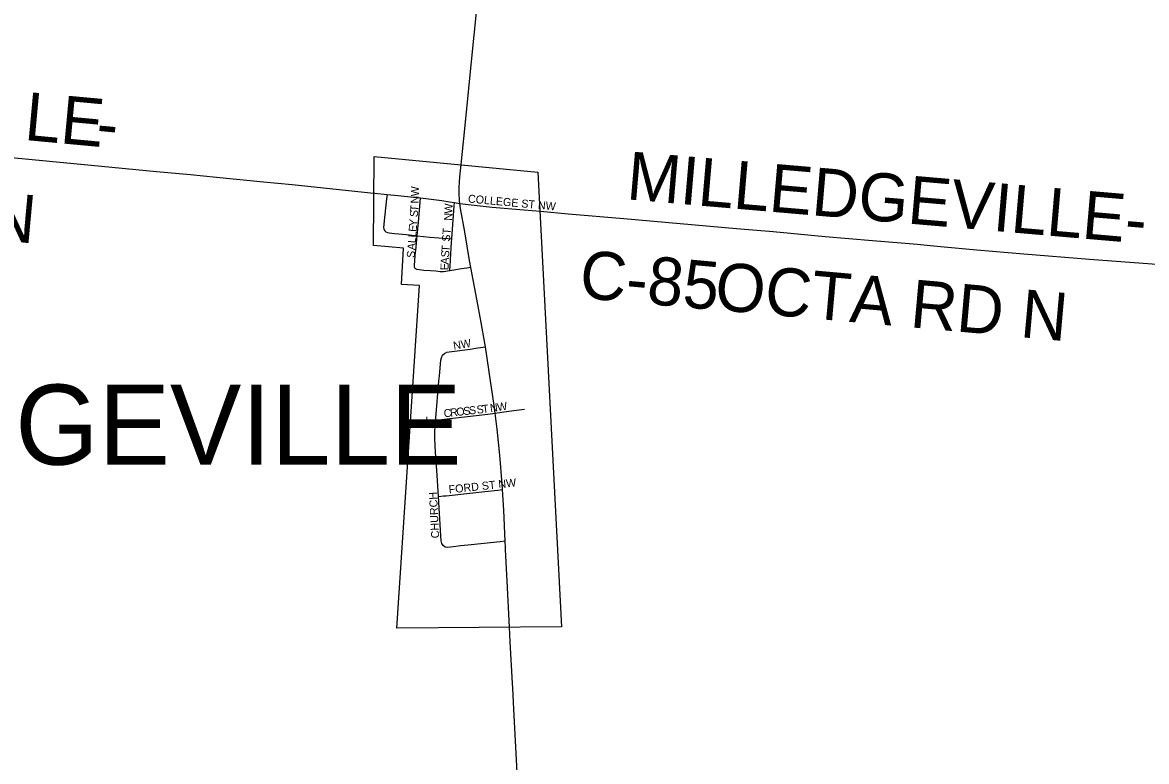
# Model space of a CAD drawing. Extents: x -49 to -8.2, y 9.4 to 23.5.
# Drawn here: x -40.683 to -40.018, y 16.323 to 16.76 of the extents above; entities that cross this region are included whole.
import ezdxf

# ---------------------------------------------------------------- set-up
doc = ezdxf.new("R2010")
doc.units = 0
for name, color, linetype in [('GM_X_City_Street', 7, 'Continuous'), ('GM_X_City_Street_Text', 7, 'Continuous'), ('GM_X_Corporation', 7, 'Continuous'), ('GM_X_Corporation_Text', 7, 'Continuous'), ('GM_X_County_Road', 7, 'Continuous'), ('GM_X_County_Road_Text', 7, 'Continuous'), ('GM_X_State_Route', 7, 'Continuous')]:
    doc.layers.add(name, color=color, linetype=linetype)

msp = doc.modelspace()

# ---------------------------------------------------------------- linework, layer by layer
at = {"layer": 'GM_X_City_Street'}
for points in [[(-40.47469, 16.65893), (-40.46752, 16.65819)], [(-40.46752, 16.65819), (-40.46779, 16.65552), (-40.46873, 16.64634), (-40.46958, 16.6387), (-40.46947, 16.63794), (-40.46922, 16.63723), (-40.46876, 16.63661), (-40.46815, 16.63617), (-40.46728, 16.6358), (-40.46623, 16.63551), (-40.46302, 16.63509), (-40.45607, 16.63447), (-40.44964, 16.6338)], [(-40.46752, 16.65819), (-40.461, 16.65752), (-40.45187, 16.65662), (-40.44779, 16.65613)], [(-40.44964, 16.6338), (-40.4487, 16.64402), (-40.44797, 16.65367), (-40.44779, 16.65613)], [(-40.44779, 16.65613), (-40.43516, 16.65461), (-40.43063, 16.65391), (-40.42764, 16.65339)], [(-40.42916, 16.63194), (-40.42778, 16.65143), (-40.42764, 16.65339)], [(-40.42764, 16.65339), (-40.42438, 16.65282)], [(-40.42438, 16.65282), (-40.41772, 16.65199), (-40.40529, 16.65072), (-40.38662, 16.64906), (-40.37681, 16.64827)], [(-40.43035, 16.613), (-40.43183, 16.61278), (-40.4328, 16.61263), (-40.43412, 16.61253), (-40.43603, 16.61252), (-40.43864, 16.61275), (-40.44186, 16.61304), (-40.44571, 16.61332), (-40.44987, 16.61379), (-40.45022, 16.61394), (-40.45048, 16.61415), (-40.45077, 16.61443), (-40.45101, 16.61475), (-40.45117, 16.61516), (-40.45124, 16.61549), (-40.4513, 16.61592), (-40.45133, 16.61624), (-40.45078, 16.62213), (-40.45032, 16.62702), (-40.44984, 16.63167), (-40.44964, 16.6338)], [(-40.44964, 16.6338), (-40.44224, 16.63304), (-40.43152, 16.63214), (-40.42916, 16.63194)], [(-40.43035, 16.613), (-40.43029, 16.61449), (-40.43024, 16.61545), (-40.42993, 16.61978), (-40.4293, 16.63001), (-40.42916, 16.63194)], [(-40.41786, 16.61498), (-40.42027, 16.61463), (-40.42337, 16.61419), (-40.42795, 16.61341), (-40.43035, 16.613)], [(-40.43865, 16.52482), (-40.43855, 16.52616), (-40.43678, 16.54782), (-40.43653, 16.5509), (-40.4356, 16.56017), (-40.43528, 16.56168), (-40.43465, 16.5631), (-40.43359, 16.56421), (-40.43219, 16.56486), (-40.43067, 16.56517), (-40.4276, 16.56561), (-40.41835, 16.56676), (-40.41374, 16.56743), (-40.40935, 16.56808)], [(-40.40358, 16.52887), (-40.3985, 16.52971), (-40.39083, 16.53068), (-40.38623, 16.53125)], [(-40.43696, 16.47966), (-40.43785, 16.49208), (-40.43878, 16.50602), (-40.43919, 16.51377), (-40.43915, 16.51843), (-40.43879, 16.52307), (-40.43865, 16.52482)], [(-40.43865, 16.52482), (-40.43377, 16.52534), (-40.41483, 16.52747), (-40.40794, 16.52827), (-40.40358, 16.52887)], [(-40.43696, 16.47966), (-40.43414, 16.47994), (-40.43261, 16.48009), (-40.42035, 16.48146), (-40.40963, 16.48257), (-40.40198, 16.4834), (-40.39917, 16.48371)], [(-40.39765, 16.45323), (-40.40067, 16.45289), (-40.41764, 16.45099), (-40.42381, 16.45036), (-40.42996, 16.4496), (-40.43152, 16.4495), (-40.43304, 16.44975), (-40.43435, 16.45055), (-40.43518, 16.45184), (-40.43553, 16.45335), (-40.43573, 16.45645), (-40.43696, 16.47966)]]:
    msp.add_lwpolyline(points, dxfattribs=at)
at = {"layer": 'GM_X_Corporation'}
msp.add_lwpolyline([(-40.47503, 16.68061), (-40.37833, 16.67144), (-40.36427, 16.4026), (-40.4618, 16.40178), (-40.4482, 16.60427), (-40.45886, 16.60498), (-40.45768, 16.62653), (-40.47546, 16.62795)], close=True, dxfattribs=at)
at = {"layer": 'GM_X_County_Road'}
for points in [[(-40.90135, 16.70783), (-40.89314, 16.70715), (-40.84518, 16.70339), (-40.81889, 16.70112), (-40.80964, 16.70005), (-40.80197, 16.69886), (-40.79285, 16.69703), (-40.7671, 16.69124), (-40.74738, 16.68698), (-40.73976, 16.68553), (-40.73209, 16.68433), (-40.72285, 16.68319), (-40.6425, 16.6756), (-40.60388, 16.67186), (-40.5838, 16.66994), (-40.56835, 16.66846), (-40.54056, 16.66566), (-40.52357, 16.66402), (-40.50505, 16.66203), (-40.47726, 16.65919), (-40.47469, 16.65893)], [(-40.37681, 16.64827), (-40.36037, 16.64683)], [(-40.36037, 16.64683), (-40.32733, 16.64395), (-40.26083, 16.63812), (-40.23917, 16.63624), (-40.20825, 16.63337), (-40.18042, 16.63097), (-40.1634, 16.62957), (-40.15393, 16.62872), (-40.14021, 16.62749), (-40.11857, 16.62553), (-40.09073, 16.62314), (-40.05205, 16.62001), (-39.99632, 16.61578), (-39.96691, 16.61352), (-39.94058, 16.61162), (-39.91949, 16.61001)]]:
    msp.add_lwpolyline(points, dxfattribs=at)
at = {"layer": 'GM_X_State_Route'}
for points in [[(-40.42367, 16.67584), (-40.42128, 16.69902), (-40.41705, 16.74076), (-40.41477, 16.76395), (-40.41235, 16.78713), (-40.4081, 16.82887), (-40.40739, 16.83604)], [(-40.39748, 16.44923), (-40.39765, 16.45323), (-40.39846, 16.47152), (-40.39917, 16.48371), (-40.39936, 16.48703), (-40.40085, 16.50406), (-40.40244, 16.51952), (-40.40358, 16.52887), (-40.40413, 16.5334), (-40.40707, 16.55338), (-40.40935, 16.56808), (-40.40969, 16.57028), (-40.41176, 16.58253), (-40.41434, 16.59628), (-40.41786, 16.61498), (-40.41865, 16.61921), (-40.42155, 16.63606), (-40.42401, 16.64985), (-40.42438, 16.65282), (-40.4246, 16.6545), (-40.42493, 16.65918), (-40.42493, 16.66232), (-40.42453, 16.66855), (-40.42367, 16.67584)], [(-40.39504, 16.40226), (-40.39647, 16.42959), (-40.39743, 16.44823), (-40.39748, 16.44923)], [(-40.39458, 16.39377), (-40.39504, 16.40226)], [(-40.39016, 16.30884), (-40.39248, 16.35382), (-40.3931, 16.36622), (-40.39326, 16.36932), (-40.39458, 16.39377)]]:
    msp.add_lwpolyline(points, dxfattribs=at)

# ---------------------------------------------------------------- texts
at = {"layer": 'GM_X_City_Street_Text'}
for s, height, rotation, p in [('W', 0.00473, 89.96073, (-40.44868, 16.6571)), ('N', 0.00473, 88.5966, (-40.44879, 16.65281)), ('COLLEGE ST NW', 0.0047348, 354.80647, (-40.41977, 16.65346)), ('T', 0.00473, 85.71008, (-40.44913, 16.64798)), ('W', 0.00473, 87.72157, (-40.4289, 16.64681)), ('Y', 0.00473, 85.73373, (-40.44978, 16.63925)), ('S', 0.00473, 85.72051, (-40.44938, 16.64466)), ('N', 0.00473, 87.33293, (-40.4291, 16.64261)), ('L', 0.00473, 85.7348, (-40.45028, 16.63261)), ('E', 0.00473, 85.7348, (-40.45003, 16.63593)), ('ST', 0.004735, 85.60322, (-40.43034, 16.63014)), ('A', 0.00473, 85.72478, (-40.45083, 16.62513)), ('L', 0.00473, 85.70607, (-40.45052, 16.62928)), ('S', 0.00473, 85.73332, (-40.45118, 16.62055)), ('S', 0.00473, 86.30949, (-40.43084, 16.62082)), ('T', 0.00473, 86.28223, (-40.43062, 16.62414)), ('E', 0.00473, 88.3876, (-40.43118, 16.61337)), ('A', 0.00473, 86.56679, (-40.43109, 16.61666)), ('NW', 0.004735, 9.46675, (-40.42794, 16.56637)), ('C', 0.00473, 6.35092, (-40.43372, 16.52637)), ('R', 0.00473, 6.35142, (-40.42999, 16.52679)), ('O', 0.00473, 6.35859, (-40.42627, 16.5272)), ('S', 0.00473, 6.35226, (-40.42212, 16.52767)), ('S', 0.00473, 6.34631, (-40.41881, 16.52804)), ('S', 0.00473, 6.34631, (-40.41426, 16.52854)), ('T', 0.00473, 6.34631, (-40.41094, 16.52891)), ('N', 0.00473, 7.56555, (-40.40628, 16.52943)), ('W', 0.00473, 9.38384, (-40.40199, 16.53)), ('S', 0.00473, 89.86338, (-40.43951, 16.51965)), ('T', 0.00473, 88.98915, (-40.43951, 16.52297)), ('FORD ST NW', 0.004735, 6.04412, (-40.43079, 16.48137)), ('CHURCH', 0.004735, 92.96295, (-40.4366, 16.45502))]:
    msp.add_text(s, height=height, rotation=rotation, dxfattribs=at).set_placement(p)
at = {"layer": 'GM_X_Corporation_Text'}
msp.add_text('MILLEDGEVILLE', height=0.0473485, rotation=0.00001, dxfattribs=at).set_placement((-40.91612, 16.49841))
at = {"layer": 'GM_X_County_Road_Text'}
for s, height, rotation, p in [('L', 0.02841, 354.6974, (-40.68258, 16.69048)), ('E', 0.02841, 354.70142, (-40.66142, 16.68852)), ('-', 0.02841, 354.70028, (-40.64026, 16.68655)), ('MILLEDGEVILLE-', 0.0284091, 355.085, (-40.32636, 16.65537)), ('N', 0.02841, 354.71575, (-40.70383, 16.63171)), ('C-85', 0.028409, 354.83691, (-40.35431, 16.59716)), ('OCTA RD N', 0.028409, 354.87932, (-40.27429, 16.59008))]:
    msp.add_text(s, height=height, rotation=rotation, dxfattribs=at).set_placement(p)

doc.saveas('drawing.dxf')
